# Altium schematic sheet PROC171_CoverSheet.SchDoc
size 431 x 279 mm; Date: Not shown in title block; ApprovedBy: Not shown in title block; CheckedBy: Not shown in title block; Author: Not shown in title block; CompanyName: Not shown in title block; Engineer: Shrinivas/Rakesh; Organization: Not shown in title block; Address1: Not shown in title block; Address2: Not shown in title block; Address3: Not shown in title block; Address4: Not shown in title block; DocumentNumber: 1; Rev: A; SheetNumber: 1; SheetTotal: 27; PageSetup: Record=PageOptions¦CenterHorizontal=True¦CenterVertical=True¦PrintScale=1.00¦XCorrection=1.00¦YCorrection=1.00¦PrintKind=0¦BorderSize=5000000¦LeftOffset=0¦BottomOffset=0¦Orientation=2¦PaperLength=1000¦PaperWidth=1000¦Scale=100¦PaperSource=15¦PrintQuality=600¦MediaType=1¦DitherType=10¦PaperKind=Letter¦PrintScaleMode=1; Revision: E1
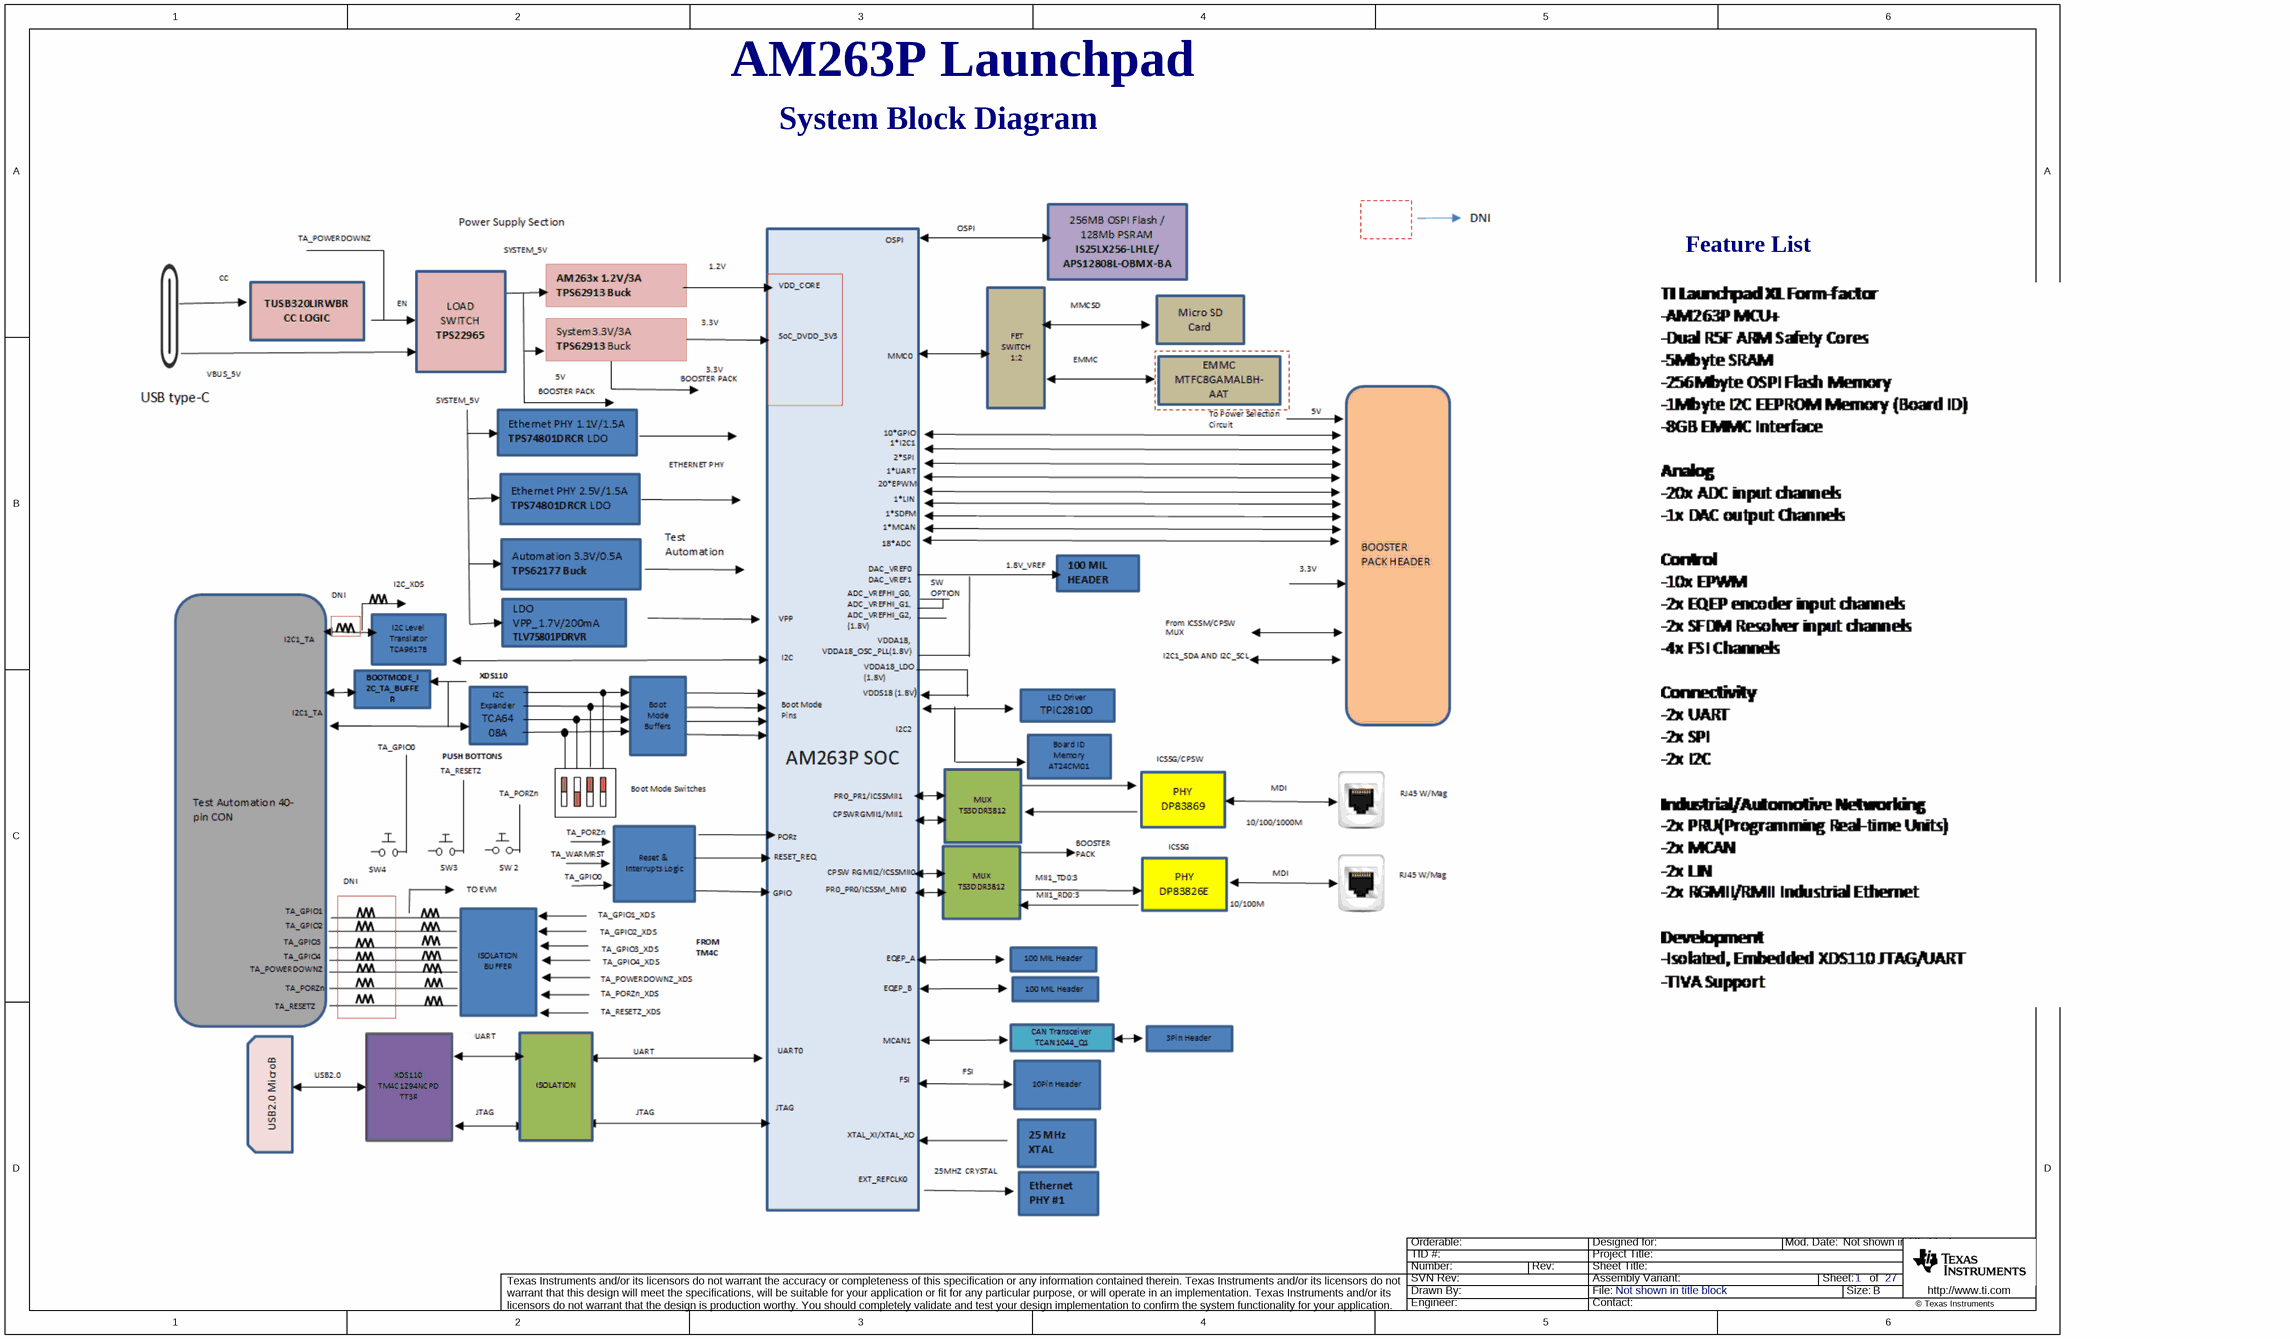
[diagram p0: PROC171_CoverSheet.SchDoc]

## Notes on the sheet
- AM263P Launchpad
- System Block Diagram
- Feature List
